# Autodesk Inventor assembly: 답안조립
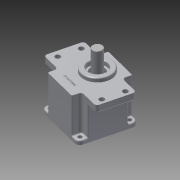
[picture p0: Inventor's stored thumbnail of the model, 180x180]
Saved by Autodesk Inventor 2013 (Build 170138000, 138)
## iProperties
Created: 2015-07
Part Number: 답안조립
Document SubType Name: Assembly
Designer: user
Author: user
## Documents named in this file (10)
- C:\Users\user\Desktop\450734V1005\답안조립.iam
- C:\Users\user\Desktop\450734V1005\메인축.ipt
- C:\Users\user\Desktop\450734V1005\베어링 6003.ipt
- 베어링 6003.ipt
- C:\Users\user\Desktop\450734V1005\본체.ipt
- C:\Users\user\Desktop\450734V1005\베어링 608.ipt
- 베어링 608.ipt
- C:\Users\user\Desktop\450734V1005\서브축.ipt
- C:\Users\user\Desktop\450734V1005\커버.ipt
- C:\Users\user\Desktop\450734V1005\M4x0.5x16.ipt
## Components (4 placed, 1 different names)
1. M4x0.5x12:1 — 각도:1
2. M4x0.5x12:2
3. M4x0.5x12:3
4. M4x0.5x12:4
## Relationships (1: Angle 1)
- 각도:1 [Angle]: M4x0.5x12:1
